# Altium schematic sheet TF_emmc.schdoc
size 420 x 297 mm; Symbol: Drawing-Symbol_A4; Company: 嘉立创EDA; Version: V1.0; Page Size: A4; @Project Name: A113 Android MircroPhone; @Page Count: 3; @Update Date: 2025-08-09; @Create Date: 2025-08-09; @Schematic Name: Schematic1; @Page No: 3; @Page Name: TF/emmc; @Create Time: 14:19:15; @Update Time: 14:19:31; Border: 1; Width: 1655; Height: 1170; Region Start: 1; X Region Count: 6; Y Region Count: 4; Blade Width: 10; Title Block Position: 3; @Board Name: Board1; Device: Drawing-Symbol_A4
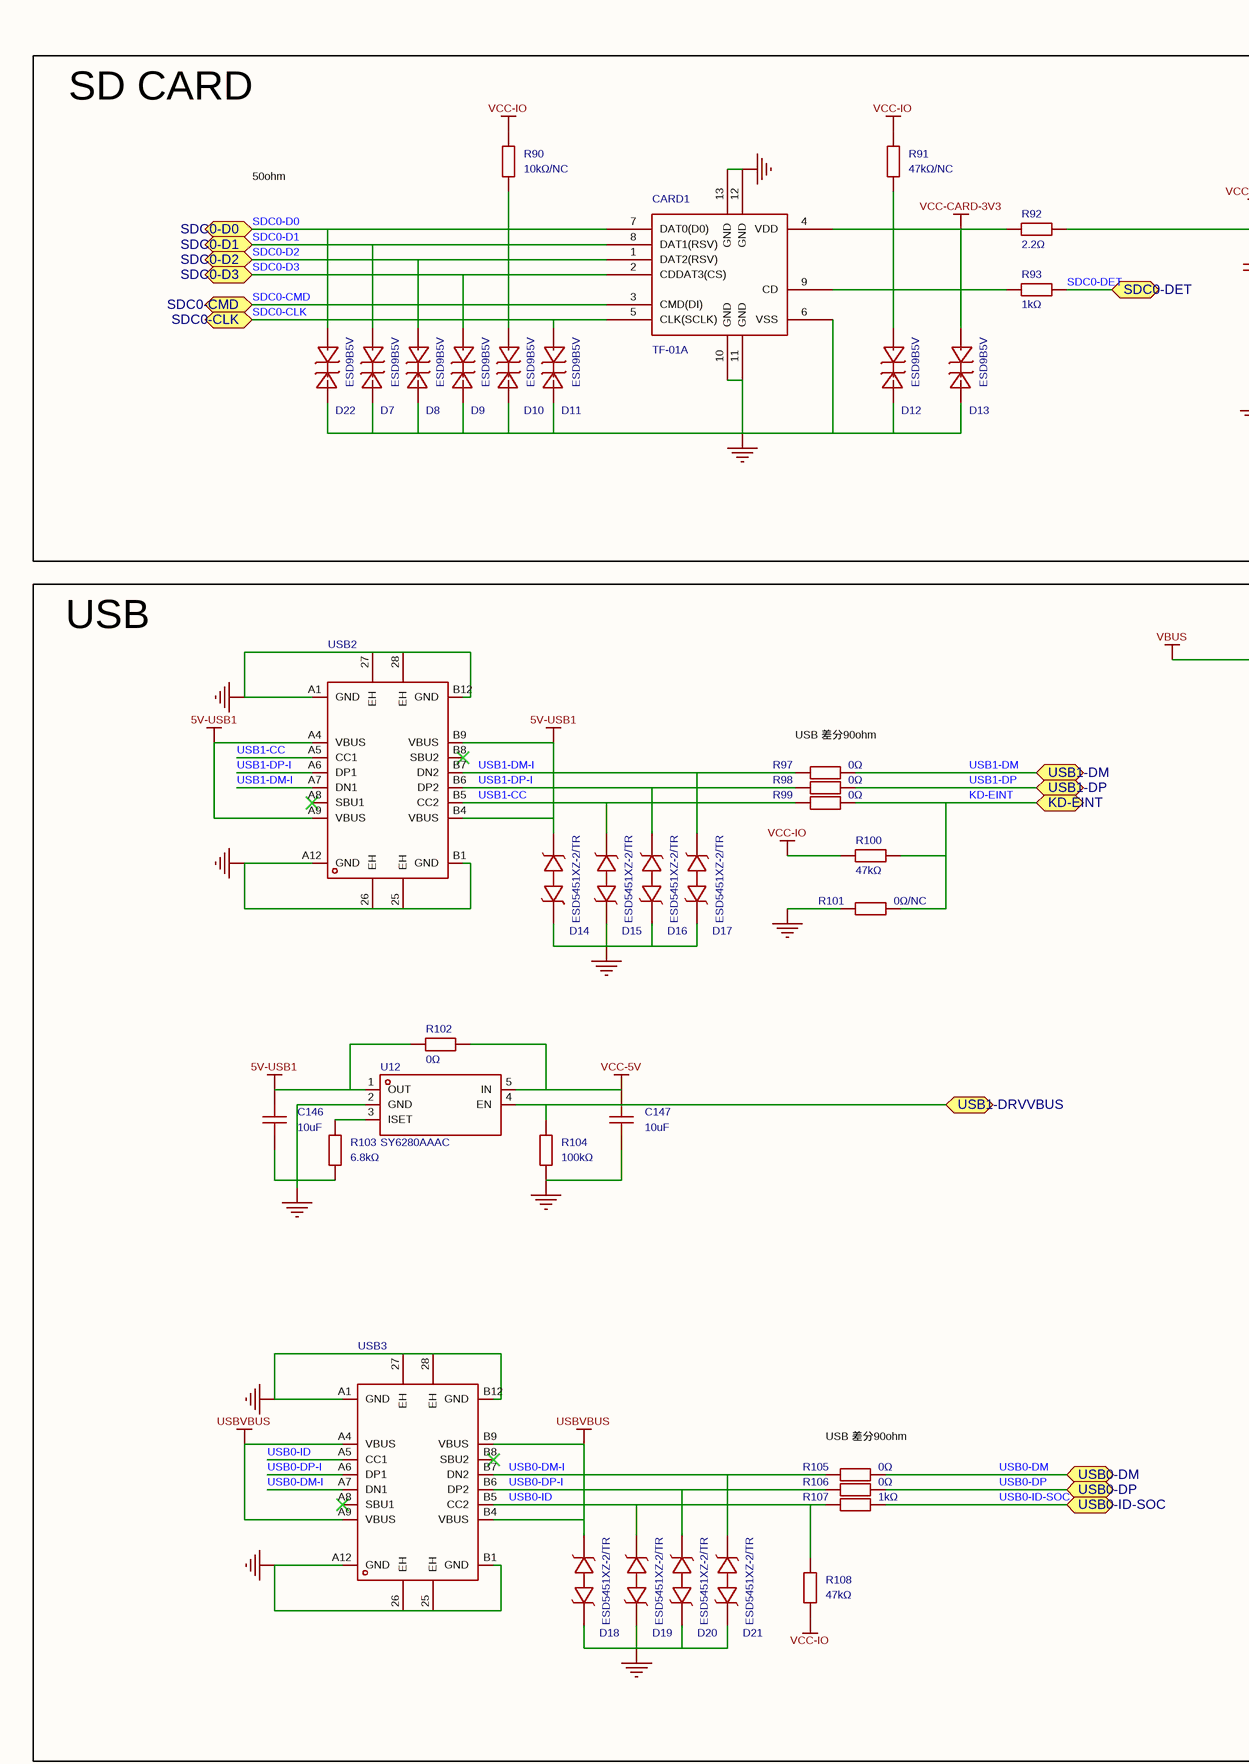
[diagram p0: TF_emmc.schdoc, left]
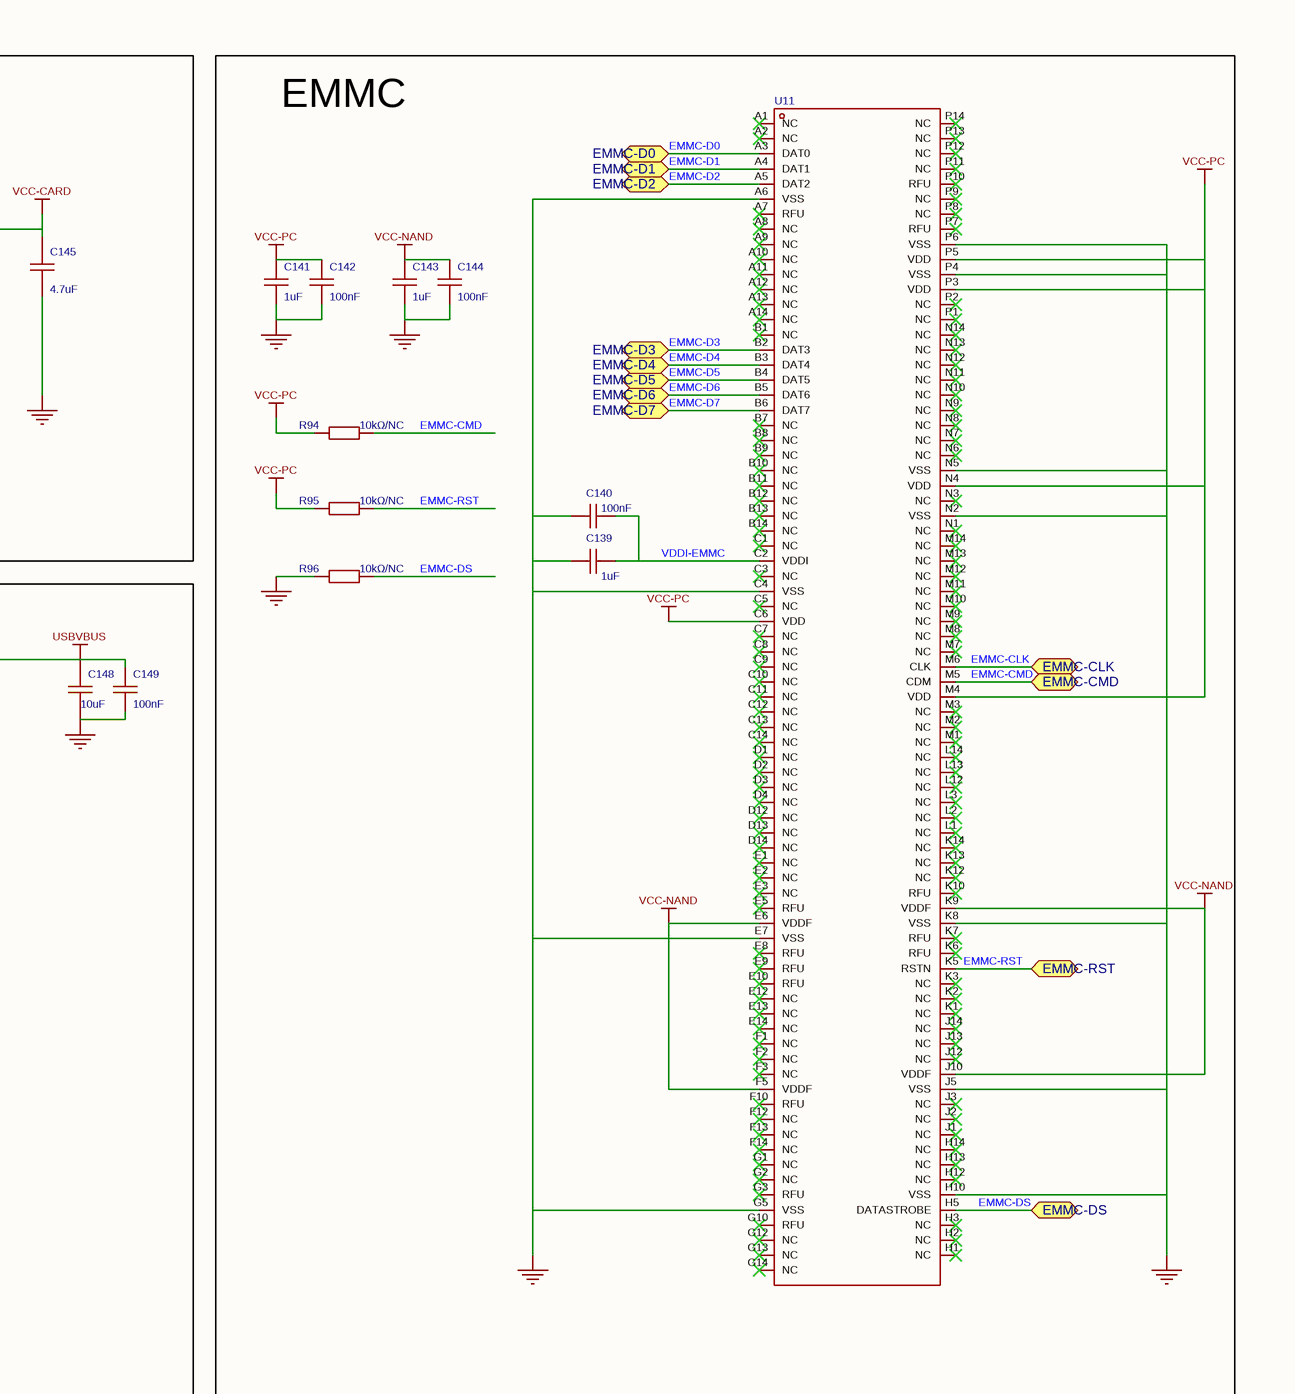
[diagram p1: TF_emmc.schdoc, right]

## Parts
C139  1uF  [C0402]
C140  100nF  [C0402]
C141  1uF  [C0402]
C142  100nF  [C0402]
C143  1uF  [C0402]
C144  100nF  [C0402]
C145  4.7uF  [C0402]
C146  10uF  [C0603]
C147  10uF  [C0603]
C148  10uF  [C0603]
C149  100nF  [C0402]
CARD1  TF-01A  [TF-SMD_TF-01A]
D7  ESD9B5V  [SOD-923_L0.8-W0.6-LS1.0-BI-1]
D8  ESD9B5V  [SOD-923_L0.8-W0.6-LS1.0-BI-1]
D9  ESD9B5V  [SOD-923_L0.8-W0.6-LS1.0-BI-1]
D10  ESD9B5V  [SOD-923_L0.8-W0.6-LS1.0-BI-1]
D11  ESD9B5V  [SOD-923_L0.8-W0.6-LS1.0-BI-1]
D12  ESD9B5V  [SOD-923_L0.8-W0.6-LS1.0-BI-1]
D13  ESD9B5V  [SOD-923_L0.8-W0.6-LS1.0-BI-1]
D14  ESD5451XZ-2/TR  [X3-DFN0603-2_L0.6-W0.3-BI]
D15  ESD5451XZ-2/TR  [X3-DFN0603-2_L0.6-W0.3-BI]
D16  ESD5451XZ-2/TR  [X3-DFN0603-2_L0.6-W0.3-BI]
D17  ESD5451XZ-2/TR  [X3-DFN0603-2_L0.6-W0.3-BI]
D18  ESD5451XZ-2/TR  [X3-DFN0603-2_L0.6-W0.3-BI]
D19  ESD5451XZ-2/TR  [X3-DFN0603-2_L0.6-W0.3-BI]
D20  ESD5451XZ-2/TR  [X3-DFN0603-2_L0.6-W0.3-BI]
D21  ESD5451XZ-2/TR  [X3-DFN0603-2_L0.6-W0.3-BI]
D22  ESD9B5V  [SOD-923_L0.8-W0.6-LS1.0-BI-1]
R90  10kΩ/NC  [R0402]
R91  47kΩ/NC  [R0402]
R92  2.2Ω  [R0603]
R93  1kΩ  [R0402]
R94  10kΩ/NC  [R0402]
R95  10kΩ/NC  [R0402]
R96  10kΩ/NC  [R0402]
R97  0Ω  [R0402]
R98  0Ω  [R0402]
R99  0Ω  [R0402]
R100  47kΩ  [R0402]
R101  0Ω/NC  [R0402]
R102  0Ω  [R0402]
R103  6.8kΩ  [R0402]
R104  100kΩ  [R0402]
R105  0Ω  [R0402]
R106  0Ω  [R0402]
R107  1kΩ  [R0402]
R108  47kΩ  [R0402]
U11  KLMBG2JETD-B041  [BGA-153_L13.0-W11.5-P0.50-TL_KLM8G1GEME-B041]  (value not drawn)
U12  SY6280AAAC  [TSOT-23-5_L2.9-W1.6-P0.95-LS2.8-BL]
USB2  TYPEC-307DSW-ACP16  [USB-C-SMD_XUNPU_TYPEC-304A-ACP16L]  (value not drawn)
USB3  TYPEC-307DSW-ACP16  [USB-C-SMD_XUNPU_TYPEC-304A-ACP16L]  (value not drawn)

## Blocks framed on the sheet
SD CARD: C145 CARD1 D7-D13 D22 R90-R93
EMMC: C139-C144 R94-R96 U11
USB: C146-C149 D14-D21 R97-R108 U12 USB2 USB3

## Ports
EMMC-CLK (bidir), EMMC-CMD (bidir), EMMC-D0 (bidir), EMMC-D1 (bidir), EMMC-D2 (bidir), EMMC-D3 (bidir), EMMC-D4 (bidir), EMMC-D5 (bidir), EMMC-D6 (bidir), EMMC-D7 (bidir), EMMC-DS (bidir), EMMC-RST (bidir), KD-EINT (bidir), SDC0-CLK (bidir), SDC0-CMD (bidir), SDC0-D0 (bidir), SDC0-D1 (bidir), SDC0-D2 (bidir), SDC0-D3 (bidir), SDC0-DET (bidir), USB0-DM (bidir), USB0-DP (bidir), USB0-ID-SOC (bidir), USB1-DM (bidir), USB1-DP (bidir), USB1-DRVVBUS (bidir)

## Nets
5V-USB1: C146.2 D14.2 R102.1 U12.1(OUT) USB2.A4(VBUS) USB2.A9(VBUS) USB2.B4(VBUS) USB2.B9(VBUS)
GND: C139.1 C140.2 C141.1 C142.2 C143.1 C144.2 C145.1 C146.1 C147.1 C148.1 C149.2 CARD1.6(VSS) CARD1.10(GND) CARD1.11(GND) CARD1.12(GND) CARD1.13(GND) D7.1(C) D8.1(C) D9.1(C) D10.1(C) D11.1(C) D12.1(C) D13.1(C) D14.1 D15.1 D16.1 D17.1 D18.1 D19.1 D20.1 D21.1 D22.1(C) R96.1 R101.1 R103.1 R104.1 U11.A6(VSS) U11.C4(VSS) U11.E7(VSS) U11.G5(VSS) U11.H10(VSS) U11.J5(VSS) U11.K8(VSS) U11.N2(VSS) U11.N5(VSS) U11.P4(VSS) U11.P6(VSS) U12.2(GND) USB2.25(EH) USB2.26(EH) USB2.27(EH) USB2.28(EH) USB2.A1(GND) USB2.A12(GND) USB2.B1(GND) USB2.B12(GND) USB3.25(EH) USB3.26(EH) USB3.27(EH) USB3.28(EH) USB3.A1(GND) USB3.A12(GND) USB3.B1(GND) USB3.B12(GND)
USBVBUS: C148.2 C149.1 D18.2 USB3.A4(VBUS) USB3.A9(VBUS) USB3.B4(VBUS) USB3.B9(VBUS)  [also labelled VBUS]
VCC-5V: C147.2 R102.2 U12.5(IN)
VCC-CARD: C145.2 R92.2
VCC-CARD-3V3: CARD1.4(VDD) D13.2(A) R92.1
VCC-IO: R90.2 R91.2 R100.2 R108.2
VCC-NAND: C143.2 C144.1 U11.E6(VDDF) U11.F5(VDDF) U11.J10(VDDF) U11.K9(VDDF)
VCC-PC: C141.2 C142.1 R94.1 R95.1 U11.C6(VDD) U11.M4(VDD) U11.N4(VDD) U11.P3(VDD) U11.P5(VDD)
EMMC-CLK: U11.M6(CLK) ; port EMMC-CLK
EMMC-CMD: R94.2 U11.M5(CDM) ; port EMMC-CMD
EMMC-D0: U11.A3(DAT0) ; port EMMC-D0
EMMC-D1: U11.A4(DAT1) ; port EMMC-D1
EMMC-D2: U11.A5(DAT2) ; port EMMC-D2
EMMC-D3: U11.B2(DAT3) ; port EMMC-D3
EMMC-D4: U11.B3(DAT4) ; port EMMC-D4
EMMC-D5: U11.B4(DAT5) ; port EMMC-D5
EMMC-D6: U11.B5(DAT6) ; port EMMC-D6
EMMC-D7: U11.B6(DAT7) ; port EMMC-D7
EMMC-DS: R96.2 U11.H5(DATASTROBE) ; port EMMC-DS
EMMC-RST: R95.2 U11.K5(RSTN) ; port EMMC-RST
KD-EINT: R99.2 R100.1 R101.2 ; port KD-EINT
SDC0-CLK: CARD1.5(CLK(SCLK)) D11.2(A) ; port SDC0-CLK
SDC0-CMD: CARD1.3(CMD(DI)) D10.2(A) R90.1 ; port SDC0-CMD
SDC0-D0: CARD1.7(DAT0(D0)) D22.2(A) ; port SDC0-D0
SDC0-D1: CARD1.8(DAT1(RSV)) D7.2(A) ; port SDC0-D1
SDC0-D2: CARD1.1(DAT2(RSV)) D8.2(A) ; port SDC0-D2
SDC0-D3: CARD1.2(CDDAT3(CS)) D9.2(A) ; port SDC0-D3
SDC0-DET: R93.2 ; port SDC0-DET
USB0-DM: R105.2 ; port USB0-DM
USB0-DM-I: D21.2 R105.1 USB3.A7(DN1) USB3.B7(DN2)
USB0-DP: R106.2 ; port USB0-DP
USB0-DP-I: D20.2 R106.1 USB3.A6(DP1) USB3.B6(DP2)
USB0-ID: D19.2 R107.1 R108.1 USB3.A5(CC1) USB3.B5(CC2)
USB0-ID-SOC: R107.2 ; port USB0-ID-SOC
USB1-CC: D15.2 R99.1 USB2.A5(CC1) USB2.B5(CC2)
USB1-DM: R97.2 ; port USB1-DM
USB1-DM-I: D17.2 R97.1 USB2.A7(DN1) USB2.B7(DN2)
USB1-DP: R98.2 ; port USB1-DP
USB1-DP-I: D16.2 R98.1 USB2.A6(DP1) USB2.B6(DP2)
USB1-DRVVBUS: R104.2 U12.4(EN) ; port USB1-DRVVBUS
VDDI-EMMC: C139.2 C140.1 U11.C2(VDDI)
NetCARD1_9: CARD1.9(CD) D12.2(A) R91.1 R93.1
NetR103_2: R103.2 U12.3(ISET)

Not connected (* = marked no-connect by the designer): U11 A1(NC)* A2(NC)* A7(RFU)* A8(NC)* A9(NC)* A10(NC)* A11(NC)* A12(NC)* A13(NC)* A14(NC)* B1(NC)* B7(NC)* B8(NC)* B9(NC)* B10(NC)* B11(NC)* B12(NC)* B13(NC)* B14(NC)* C1(NC)* C3(NC)* C5(NC)* C7(NC)* C8(NC)* C9(NC)* C10(NC)* C11(NC)* C12(NC)* C13(NC)* C14(NC)* D1(NC)* D2(NC)* D3(NC)* D4(NC)* D12(NC)* D13(NC)* D14(NC)* E1(NC)* E2(NC)* E3(NC)* E5(RFU)* E8(RFU)* E9(RFU)* E10(RFU)* E12(NC)* E13(NC)* E14(NC)* F1(NC)* F2(NC)* F3(NC)* F10(RFU)* F12(NC)* F13(NC)* F14(NC)* G1(NC)* G2(NC)* G3(RFU)* G10(RFU)* G12(NC)* G13(NC)* G14(NC)* H1(NC)* H2(NC)* H3(NC)* H12(NC)* H13(NC)* H14(NC)* J1(NC)* J2(NC)* J3(NC)* J12(NC)* J13(NC)* J14(NC)* K1(NC)* K2(NC)* K3(NC)* K6(RFU)* K7(RFU)* K10(RFU)* K12(NC)* K13(NC)* K14(NC)* L1(NC)* L2(NC)* L3(NC)* L12(NC)* L13(NC)* L14(NC)* M1(NC)* M2(NC)* M3(NC)* M7(NC)* M8(NC)* M9(NC)* M10(NC)* M11(NC)* M12(NC)* M13(NC)* M14(NC)* N1(NC)* N3(NC)* N6(NC)* N7(NC)* N8(NC)* N9(NC)* N10(NC)* N11(NC)* N12(NC)* N13(NC)* N14(NC)* P1(NC)* P2(NC)* P7(RFU)* P8(NC)* P9(NC)* P10(RFU)* P11(NC)* P12(NC)* P13(NC)* P14(NC)*; USB2 A8(SBU1)* B8(SBU2)*; USB3 A8(SBU1)* B8(SBU2)*

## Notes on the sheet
- 50ohm
- USB 差分90ohm

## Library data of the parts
C139 C141 C143 = CL05A105KA5NQNC: 容值:1uF;精度:±10%;额定电压:25V;材质(温度系数):X5R;; Manufacturer: SAMSUNG(三星); Symbol: CL05A105KP5NNNC; AddInBom: yes; ModelId: 36a51122f27c49738f86b3bfa98863e0; ModelName: C0402_L1.0-W0.5-H0.5; ModelTransform: 39.37,19.685,0,0,0,0,0,0,0; Tolerance: ±10%; Voltage Rated: 25V; Temperature Coefficient: X5R
C140 C142 C144 C149 = CL05B104KO5NNNC: 容值:100nF;精度:±10%;额定电压:16V;材质(温度系数):X7R;; Manufacturer: SAMSUNG(三星); AddInBom: yes; ModelId: 36a51122f27c49738f86b3bfa98863e0; ModelName: C0402_L1.0-W0.5-H0.5; ModelTransform: 39.37,19.685,0,0,0,0,0,0,0; Tolerance: ±10%; Voltage Rated: 16V; Temperature Coefficient: X7R
C145 = CL05A475MQ5NRNC: 容值:4.7uF;精度:±20%;额定电压:6.3V;材质(温度系数):X5R;; Manufacturer: SAMSUNG(三星); Symbol: CL05A475MQ5NRNC_C307423; AddInBom: yes; ModelId: 36a51122f27c49738f86b3bfa98863e0; ModelName: C0402_L1.0-W0.5-H0.5; ModelTransform: 39.37,19.685,0,0,0,0,0,0,0; Tolerance: ±20%; Voltage Rated: 6.3V; Temperature Coefficient: X5R
C146-C148 = CL10A106KP8NNNC: 容值:10uF;精度:±10%;额定电压:10V;材质(温度系数):X5R;; Manufacturer: SAMSUNG(三星); AddInBom: yes; ModelId: ac125912035d415993ca9572d50418b1; ModelName: C0603_L1.6-W0.8-H0.8; ModelTransform: 62.992,31.496,0,0,0,0,0,0,0; Tolerance: ±10%; Voltage Rated: 10V; Temperature Coefficient: X5R
CARD1 = TF-01A_C91145: 工作温度范围:-;本体最大高度:-;触头镀层:-;连接器类型:卡座;卡类型:MicroSD卡(TF卡);焊接温度(最大值):-;触头材质:-;卡连接方式:自弹式;; Manufacturer: 韩国韩荣; AddInBom: yes; ModelId: 5b4be50223494db9bf5c92b2cb3c1375; ModelName: TF-SMD_L14.8-W14.5-H1.9-P1.1; ModelTransform: 629.92,600.393,0,0,0,0,0,-85.473,-23.622; Connector Type: 卡座; Card Connection Mode: 自弹式
D7-D13 D22 = ESD9B5V: Manufacturer: TECH PUBLIC(台舟); AddInBom: yes; ModelId: 2f595e76c437472fa7f031dc65d7fe13; ModelTransform: 39.37,23.622,0,0,0,0,-0.005,0,0
D14-D21 = ESD5451XZ-2/TR: 极性:双向;反向截止电压(Vrwm):5V@Max;击穿电压:5.1V;峰值脉冲电流(Ipp)@10/1000μs:8A@8/20us;最大钳位电压:10V;; Manufacturer: WILLSEMI(韦尔); AddInBom: yes; ModelId: 9933fd15dc984c8c901e0bd83425b949; ModelName: X3-DFN0603-2_L0.6-W0.3-H0.5-BI; ModelTransform: 19.431,11.811,0,0,0,0,0,0,0; Polarity: 双向; Reverse Stand-Off Voltage (Vrwm): 5V@Max; Breakdown Voltage: 5.1V; Maximum Clamping Voltage: 10V
R90 R94-R96 = RC0402FR-0710KL: 电阻类型:厚膜电阻;阻值:10kΩ;精度:±1%;功率:62.5mW;; Manufacturer: YAGEO(国巨); Standardization Check: false; AddInBom: yes; ModelId: 671aefced39d4c318694bba8bd8efd39; ModelName: R0402_L1.0-W0.5-H0.5; ModelTransform: 39.37,19.685,0,0,0,0,0,0.0005,0; Tolerance: ±1%; Power(Watts): 62.5mW; Temperature Coefficient: ±100ppm/℃; Overload Voltage (Max): 50V
R91 R100 = RC0402FR-0747KL: 电阻类型:厚膜电阻;阻值:47kΩ;精度:±1%;功率:62.5mW;; Manufacturer: YAGEO(国巨); Symbol: 0402WGF4702TCE; Standardization Check: false; AddInBom: yes; ModelId: 671aefced39d4c318694bba8bd8efd39; ModelName: R0402_L1.0-W0.5-H0.5; ModelTransform: 39.37,19.685,0,0,0,0,0,0.0005,0; Tolerance: ±1%; Power(Watts): 62.5mW; Temperature Coefficient: ±100ppm/℃; Overload Voltage (Max): 50V
R92 = RC0603FR-072R2L: 电阻类型:厚膜电阻;阻值:2.2Ω;精度:±1%;功率:100mW;; Manufacturer: YAGEO(国巨); AddInBom: yes; ModelId: fc143cca1e79419f9cd78b61e9279f08; ModelTransform: 31.8897,63.7794,0,90,0,0,0,0,0; Tolerance: ±1%; Power(Watts): 100mW; Temperature Coefficient: ±200ppm/℃; Overload Voltage (Max): 75V
R93 R107 = AC0402FR-071KL: 电阻类型:厚膜电阻;阻值:1kΩ;精度:±1%;功率:62.5mW;; Manufacturer: YAGEO(国巨); AddInBom: yes; ModelId: 671aefced39d4c318694bba8bd8efd39; ModelName: R0402_L1.0-W0.5-H0.5; ModelTransform: 39.37,19.685,0,0,0,0,0,0.0005,0; Tolerance: ±1%; Power(Watts): 62.5mW; Temperature Coefficient: ±100ppm/℃; Overload Voltage (Max): 50V
R97-R99 R102 R105 R106 = 0402WGF0000TCE: 电阻类型:厚膜电阻;阻值:0Ω;精度:±1%;功率:62.5mW;; Manufacturer: UNI-ROYAL(厚声); Symbol: RC0402JR-070RL; Standardization Check: false; AddInBom: yes; ModelId: 671aefced39d4c318694bba8bd8efd39; ModelName: R0402_L1.0-W0.5-H0.5; ModelTransform: 39.37,19.685,0,0,0,0,0,0.0005,0; Tolerance: ±1%; Power(Watts): 62.5mW; Temperature Coefficient: ±800ppm/℃; Overload Voltage (Max): 50V
R101 = RC0402JR-070RL: 电阻类型:厚膜电阻;阻值:0Ω;精度:-;功率:62.5mW;; Manufacturer: YAGEO(国巨); Standardization Check: false; AddInBom: yes; ModelId: 671aefced39d4c318694bba8bd8efd39; ModelName: R0402_L1.0-W0.5-H0.5; ModelTransform: 39.37,19.685,0,0,0,0,0,0.0005,0; Power(Watts): 62.5mW; Overload Voltage (Max): 50V
R103 = 0402WGF6801TCE: 电阻类型:厚膜电阻;阻值:6.8kΩ;精度:±1%;功率:62.5mW;; Manufacturer: UNI-ROYAL(厚声); AddInBom: yes; ModelId: 671aefced39d4c318694bba8bd8efd39; ModelName: R0402_L1.0-W0.5-H0.5; ModelTransform: 39.37,19.685,0,0,0,0,0,0.0005,0; Tolerance: ±1%; Power(Watts): 62.5mW; Temperature Coefficient: ±100ppm/℃; Overload Voltage (Max): 50V
R104 = 0402WGF1003TCE: 电阻类型:厚膜电阻;阻值:100kΩ;精度:±1%;功率:62.5mW;; Manufacturer: UNI-ROYAL(厚声); AddInBom: yes; ModelId: 671aefced39d4c318694bba8bd8efd39; ModelName: R0402_L1.0-W0.5-H0.5; ModelTransform: 39.37,19.685,0,0,0,0,0,0.0005,0; Tolerance: ±1%; Power(Watts): 62.5mW; Temperature Coefficient: ±100ppm/℃; Overload Voltage (Max): 50V
R108 = 0402WGF4702TCE: 电阻类型:厚膜电阻;阻值:47kΩ;精度:±1%;功率:62.5mW;; Manufacturer: UNI-ROYAL(厚声); Symbol: RC0402FR-0747KL; AddInBom: yes; ModelId: 671aefced39d4c318694bba8bd8efd39; ModelName: R0402_L1.0-W0.5-H0.5; ModelTransform: 39.37,19.685,0,0,0,0,0,0.0005,0; Tolerance: ±1%; Power(Watts): 62.5mW; Temperature Coefficient: ±100ppm/℃; Overload Voltage (Max): 50V
U11 = KLMBG2JETD-B041_1: Manufacturer: SAMSUNG(三星半导体); Symbol: KLMBG2JETD-B041_C5821038; AddInBom: yes; ModelId: fe93e04ecf2b428eb8a0d13e547c759b; ModelTransform: 452.755,511.81,0,0,0,0,0,0,0
U12 = SY6280AAAC: Manufacturer: silergy(矽力杰); AddInBom: yes; ModelId: b5108020abe84f7bb0f3c398b43b6e0b; ModelName: TSOT-23-5_L2.9-W1.6-H1.00-LS2.8-P0.95; ModelTransform: 110.45568,114.173,0,90,0,0,0.0005,0,0
USB2 USB3 = TYPEC-307DSW-ACP16: 连接器类型:Type-C;标准:USB 3.1;公母:母座;触点数量:16;端口数量:1;安装方式:卧贴;额定电流 - 电源:5A;工作温度范围:-25℃~+85℃;焊接温度(最大值):260℃;; Manufacturer: XUNPU(讯普); AddInBom: yes; ModelId: 0e8123b9974d49fabd59c6dee9658782; ModelTransform: 351.9678,298.4246,0,180,0,0,0,-45.276,-39.37; Connector Type: Type-C; Gender: 母座; Number of Contacts: 16; Number of Ports: 1; Current Rating - Power (Max): 5A; Welding Temperature (Max): 260℃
